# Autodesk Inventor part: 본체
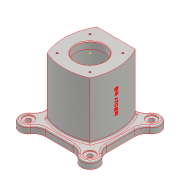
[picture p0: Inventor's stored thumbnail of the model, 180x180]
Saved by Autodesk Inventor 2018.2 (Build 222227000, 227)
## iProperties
Created: 2022-01
Part Number: 본체
Material: 알루미늄 6061
Document SubType Name: Modeling
Designer: woori
Density: 2.7 g/cm^3
Appearance: 알루미늄 - 평지
Mass: 1218.58 g
Surface Area: 907.545 cm^2
Volume: 451.327 cm^3
Author: woori
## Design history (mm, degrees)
sketch "스케치1"
  geometry: L1 (-37.928, -53)-(37.928, -53); L2 (53, -37.928)-(53, 37.928); L3 (37.928, 53)-(-37.928, 53); L4 (-53, 37.928)-(-53, -37.928); L5 (-53, -53)-(53, 53); L6 (53, -53)-(-53, 53); L7 (-90.138, 0)-(80.521, 0); L8 (0, -80.48)-(0, 80.48); L9 (0, 0)-(-73.489, 73.489); L10 (-74.306, 95.519)-(0.334, 20.879); L11 (-93.365, 72.152)-(-29.688, 8.475); C1 r 75 at (0, 0); A1 r 15.072 centre (-53, 53) between (-37.928, 53) and (-53, 37.928); A2 r 15.072 centre (-53, -53) between (-53, -37.928) and (-37.928, -53); A3 r 15.072 centre (53, -53) between (37.928, -53) and (53, -37.928); A4 r 15.072 centre (53, 53) between (53, 37.928) and (37.928, 53); 2 further points
  constraints: 22 end point, 8 point on circle, 5 centre point, 5 midpoint, 4 parallel, 2 coincident, 2 horizontal, 1 perpendicular, 1 point on line, 1 vertical, 17 other
  dimensions: "d0" = 150 diameter of C1; "d1" = 106 distance of L6.end L5.end; "d2" = 106 distance of L5.end L6.start; "d3" = 45 deg angle of L9 L8; "d4" = 15 distance between parallel lines of L9 L10; "d5" = 15 distance between parallel lines of L9 L11; "d8" = 360 deg dimension on point (0, 0) A1.centre (derived)
extrude "돌출1" new body sketch "스케치1" distance "d10" = 12; taper "d11" = 0 deg
fillet "모깎기1" dims "d12" = 20
sketch "스케치2"
  geometry: L1 (-45, -45)-(45, -45); L2 (45, -45)-(45, 45); L3 (45, 45)-(-45, 45); L4 (-45, 45)-(-45, -45); L5 (-45, -45)-(45, 45); L6 (45, -45)-(-45, 45); L7 (0, 0)-(-45, -45); L8 (-80.785, 0)-(117.597, 0); L9 (0, 53.234)-(0, -83.62); 2 further points
  constraints: 18 end point, 4 midpoint, 2 horizontal, 2 parallel, 2 point on line, 1 perpendicular, 1 vertical
  dimensions: "d16" = 90 distance of L3.end L2.end; "d17" = 90 distance of L2.end L1.end
extrude "돌출2" join sketch "스케치2" distance "d23" = 98; taper "d24" = 0 deg
sketch "스케치3" dims "d25" = 80
  geometry: L1 (-90.924, 0)-(82.794, 0); L2 (0, 150.184)-(0, -88.998); L3 (0, 0)-(-73.138, 73.138); 2 further points
  constraints: 6 end point, 3 point on line, 1 coincident, 1 horizontal, 1 vertical, 3 other
  dimensions: "d26" = 45 deg angle of L2 L3
hole "구멍1" sketch "스케치3" at (-28.284, 28.284) diameter "d27" = 3.242; stored, may be unused: countersink angle "d31" = 90 deg, drill point angle "d33" = 118 deg; dims "d28" = 9, "d29" = 4, "d30" = 2, "d32" = 11
sketch "스케치4"
  geometry: A1 r 15.072 centre (53, 53) between (61.595, 40.619) and (40.619, 61.595) reference; 2 further points
  constraints: 1 coincident
hole "구멍2" sketch "스케치4" at (53, 53) diameter "d37" = 9; stored, may be unused: countersink angle "d41" = 90 deg, drill point angle "d43" = 0 deg; dims "d38" = 9, "d39" = 18, "d40" = 2, "d42" = 14
sketch "스케치5"
  geometry: L1 (0, 189.335)-(0, -189.335); L2 (45, 110)-(-45, 110) reference; L3 (25, 110)-(25, 98); L4 (25, 98)-(37, 98); L5 (37, 98)-(37, 12); L6 (37, 12)-(25, 12); L7 (25, 12)-(25, 0); L8 (25, 110)-(0, 110); L9 (-24.19, 0)-(24.19, 0) reference; L10 (24.19, 0)-(40.619, 0) reference; L11 (24.19, 0)-(0, 0); L12 (0, 0)-(0, 110)
  constraints: 18 end point, 3 vertical, 2 collinear, 2 perpendicular, 1 horizontal, 1 midpoint, 1 point on line
  dimensions: "d47" = 50 diameter of L7 L1; "d48" = 12 distance from line of L7.end L6; "d49" = 86 distance of L4.end L5.end; "d50" = 74 diameter of L5 L1; "d51" = 50 diameter of L3 L1
revolve "회전1" sketch "스케치5" stored, may be unused: angle "d52" = 90 deg
node "작업 평면1"
sketch "스케치6"
  geometry: L1 (0, 0)-(0, 225.68); L2 (24.19, 0)-(-24.19, 0) reference; C1 r 20 at (0, 61)
  constraints: 2 end point, 1 centre point, 1 point on line, 1 vertical
  dimensions: "d54" = 61 distance from line of L2 C1.centre; "d55" = 40 diameter of C1
extrude "돌출3" join sketch "스케치6" stored distance "d56" = 98; taper "d57" = 0 deg
feature "면 기울기1" dims angle "d58" = 10 deg
sketch "스케치7"
  geometry: C1 r 18.237 at (0, 0) reference; C2 r 12 at (0, 0); 1 further point
  constraints: 1 centre point, 1 coincident
  dimensions: "d59" = 24 diameter of C2
extrude "돌출4" cut sketch "스케치7" distance "d60" = 13; taper "d61" = 0 deg
sketch "스케치8"
  geometry: C1 r 12 at (0, 0) reference; C2 r 15 at (0, 0); 1 further point
  constraints: 1 centre point, 1 coincident
  dimensions: "d62" = 30 diameter of C2
extrude "돌출5" cut sketch "스케치8" distance "d63" = 13; taper "d64" = 0 deg
sketch "스케치9"
  geometry: L1 (0, 135)-(0, -45); L2 (134.996, 1.209)-(-45, 0); L3 (-191.132, 0)-(101.132, 0); L4 (0, 113.574)-(0, -264.026); L5 (-45, -45)-(45, -45) reference; L6 (-45, 45)-(-45, -45) reference; L7 (-45, 0)-(-45, -45); L8 (-45, -45)-(0, -45); A1 r 90 centre (44.998, 0.604) between (-45, 0) and (-36.685, -37.184); A2 r 90 centre (0, 45) between (-36.685, -37.184) and (0, -45); 1 further point
  constraints: 12 end point, 5 midpoint, 4 point on circle, 3 point on line, 2 centre point, 2 vertical, 1 collinear, 1 horizontal
extrude "돌출6" cut sketch "스케치9" stored distance "d68" = 13; taper "d69" = 0 deg
sketch "스케치10"
  geometry: 1 further point
sketch "스케치11"
  geometry: L1 (0, 0)-(-75.181, 75.181); L2 (0, 0)-(0, 79.139); C1 r 40 at (0, 0); C2 r 1.621 at (-28.284, 28.284) reference; 2 further points
  constraints: 4 end point, 2 coincident, 1 centre point, 1 vertical
  dimensions: "d73" = 80 diameter of C1; "d74" = 45 deg angle of L1 L2
hole "구멍3" sketch "스케치11" at (-28.284, 28.284) diameter "d75" = 3.242; stored, may be unused: countersink angle "d79" = 90 deg, drill point angle "d81" = 118 deg; dims "d76" = 9, "d77" = 18, "d78" = 2, "d80" = 11
fillet "모깎기2" dims "d85" = 3
sketch "스케치12"
  geometry: L1 (0, 135)-(0, -45); L2 (-135, 0)-(45, 0); L3 (-154.364, 0)-(125.148, 0); L4 (0, 122.256)-(0, -99.92); L5 (45, -45)-(45, 45) reference; L6 (45, 45)-(-45, 45) reference; L7 (135, 0)-(-45, 0); L8 (-45, 45)-(-45, 0) reference; L9 (-32.942, 45)-(-45, 45); L10 (-45, 45)-(-45, 0); L11 (0, -45)-(45, -45); L12 (45, -45)-(45, 45); L13 (32.942, 45)-(45, 45); C1 r 90 at (54.13, 290.353); A1 r 90 centre (0, 45) between (0, -45) and (37.029, -37.029); A2 r 90 centre (-45, 0) between (37.029, -37.029) and (32.942, 45); A3 r 90 centre (44.998, 0.604) between (-45, 0) and (-36.685, -37.184) reference; A4 r 90 centre (45, 0) between (-32.942, 45) and (-45, 0); 1 further point
  constraints: 20 end point, 8 point on circle, 6 horizontal, 5 midpoint, 5 point on line, 4 centre point, 3 vertical, 1 collinear
extrude "돌출7" cut sketch "스케치12" stored distance "d87" = 13; taper "d88" = 0 deg
sketch "스케치13"
  geometry: L1 (0, -45)-(0, 135); L2 (-135, 0)-(45, 0); L3 (45, -45)-(45, 45) reference; L4 (0, -45)-(45, -45) reference; L5 (0, -45)-(45, -45); L6 (45, -45)-(45, 0); A1 r 90 centre (0, 45) between (0, -45) and (37.029, -37.029); A2 r 90 centre (45, 0) between (-32.942, 45) and (-45, 0) reference; A3 r 90 centre (-45, 0) between (37.029, -37.029) and (45, 0); 1 further point
  constraints: 8 end point, 4 point on circle, 3 midpoint, 2 centre point, 2 horizontal, 1 coincident, 1 collinear, 1 tangent, 1 vertical
  dimensions: "d90" = 180 diameter of A1
extrude "돌출8" cut sketch "스케치13" stored distance "d91" = 13; taper "d92" = 0 deg
sketch "스케치14"
  geometry: L1 (-45, 0)-(45, 0); L2 (45, 45)-(-32.942, 45) reference; L3 (32.942, 45)-(45, 45); L4 (45, 0)-(45, 45) reference; L5 (45, 45)-(45, 0); A1 r 90 centre (-45, 0) between (45, 0) and (32.942, 45); 1 further point
  constraints: 6 end point, 3 point on circle, 2 collinear, 1 centre point, 1 coincident, 1 horizontal, 1 point on line, 1 tangent
extrude "돌출9" cut sketch "스케치14" stored distance "d95" = 13; taper "d96" = 0 deg
fillet "모깎기3" dims "d97" = 3
fillet "모깎기4" dims "d98" = 3
chamfer "모따기1" distance "d99" = 1; stored, may be unused: second distance "d100" = 2, angle "d101" = 45 deg
chamfer "모따기2" distance "d102" = 1; stored, may be unused: second distance "d103" = 2, angle "d104" = 45 deg
fillet "모깎기5" dims "d105" = 3
node "작업 평면2"
sketch "스케치15"
  geometry: L1 (19.839, 86.118)-(19.839, 35.882); L2 (19.839, 35.882)-(-19.839, 35.882); L3 (-19.839, 35.882)-(-19.839, 86.118); L4 (-19.839, 86.118)-(19.839, 86.118); L5 (0, 86.118)-(0, 35.882); L6 (55, 79.237)-(55, 42.763) reference; L7 (19.839, 61)-(-19.839, 61); L8 (40.619, 0)-(68.072, 0) reference; 2 further points
  constraints: 4 end point, 4 midpoint, 2 other
  dimensions: "d107" = 55 distance between parallel lines of L6 L5; "d108" = 61 distance between parallel lines of L8 L7
extrude "돌출10" join sketch "스케치15" stored distance "d109" = 13; taper "d110" = 0 deg
node "솔리드1"
pattern_circular "원형 패턴1" dims angle "d14" = 360 deg
pattern_circular "원형 패턴2" dims angle "d35" = 360 deg
pattern_circular "원형 패턴3" dims angle "d45" = 360 deg
pattern_circular "원형 패턴5" dims angle "d83" = 360 deg
other parameters: "d53" = 55, "d106" = 45.5
